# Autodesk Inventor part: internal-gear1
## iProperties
Author: Administrator
Shininess: 64.0
Angle Display Precision: 2
Document Length Units: 11272
Document Angle Units: 11286
Document Time Units: 11279
Document Mass Units: 11290
Document Length Units Precision: 3
Document Angle Units Precision: 2
Compacted: True
PropertySet Name: _Private Model Information
Created: 2002-03
Part Number: internal-gear1
Material: ASTM A36 HRS
Document SubType Name: Modeling
Designer: Administrator
Control State: 0
Master: False
Checked Out: False
PropertySet Name: Design Tracking Control
Density: 0.0
Volumn: 0.0
Area: 0.0
PropertySet Name: Model Information
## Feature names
1. Extrusion1
2. Extrusion2
3. Fillet1
4. Mirror1
5. Circular Pattern1
